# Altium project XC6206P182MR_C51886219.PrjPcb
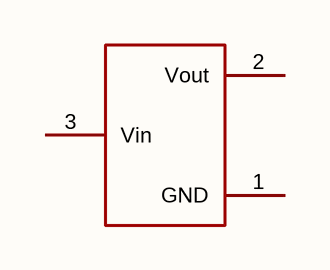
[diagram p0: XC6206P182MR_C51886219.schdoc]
1 sheet, 1 parts. Net scope: global (net labels, ports and power ports of the same name join across sheets).

## Sheet XC6206P182MR_C51886219.schdoc
size 127 x 101 mm

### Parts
U?  xc6206p182mr_c51886219  [SOT-23-3_L2.9-W1.6-P1.90-LS2.8-BR]  (value not drawn)

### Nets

Not connected (* = marked no-connect by the designer): U? 1(GND) 2(Vout) 3(Vin)

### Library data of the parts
U? = xc6206p182mr_c51886219: 输出极性:正极;工作电压:6V;输出电压:1.8V;输出电流:250mA;电源纹波抑制比(PSRR):45dB@(1kHz);输出类型:固定;; Manufacturer: TECH PUBLIC(台舟); AddInBom: yes; ModelId: 89cb27a44ab2466697082bb9fd73a7d0; ModelName: SOT-23-3L_L2.9-W1.6-H1.1-LS2.8-P0.95; ModelTransform: 114.173,110.236,0,90,0,0,0,0,0; Output Configuration: 正极; Voltage - Supply: 6V; Output Voltage: 1.8V; Output Current: 250mA; Voltage Dropout: 300mV@(50mA); standby current: 6uA; Output Type: 固定; Number of Outputs: 1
